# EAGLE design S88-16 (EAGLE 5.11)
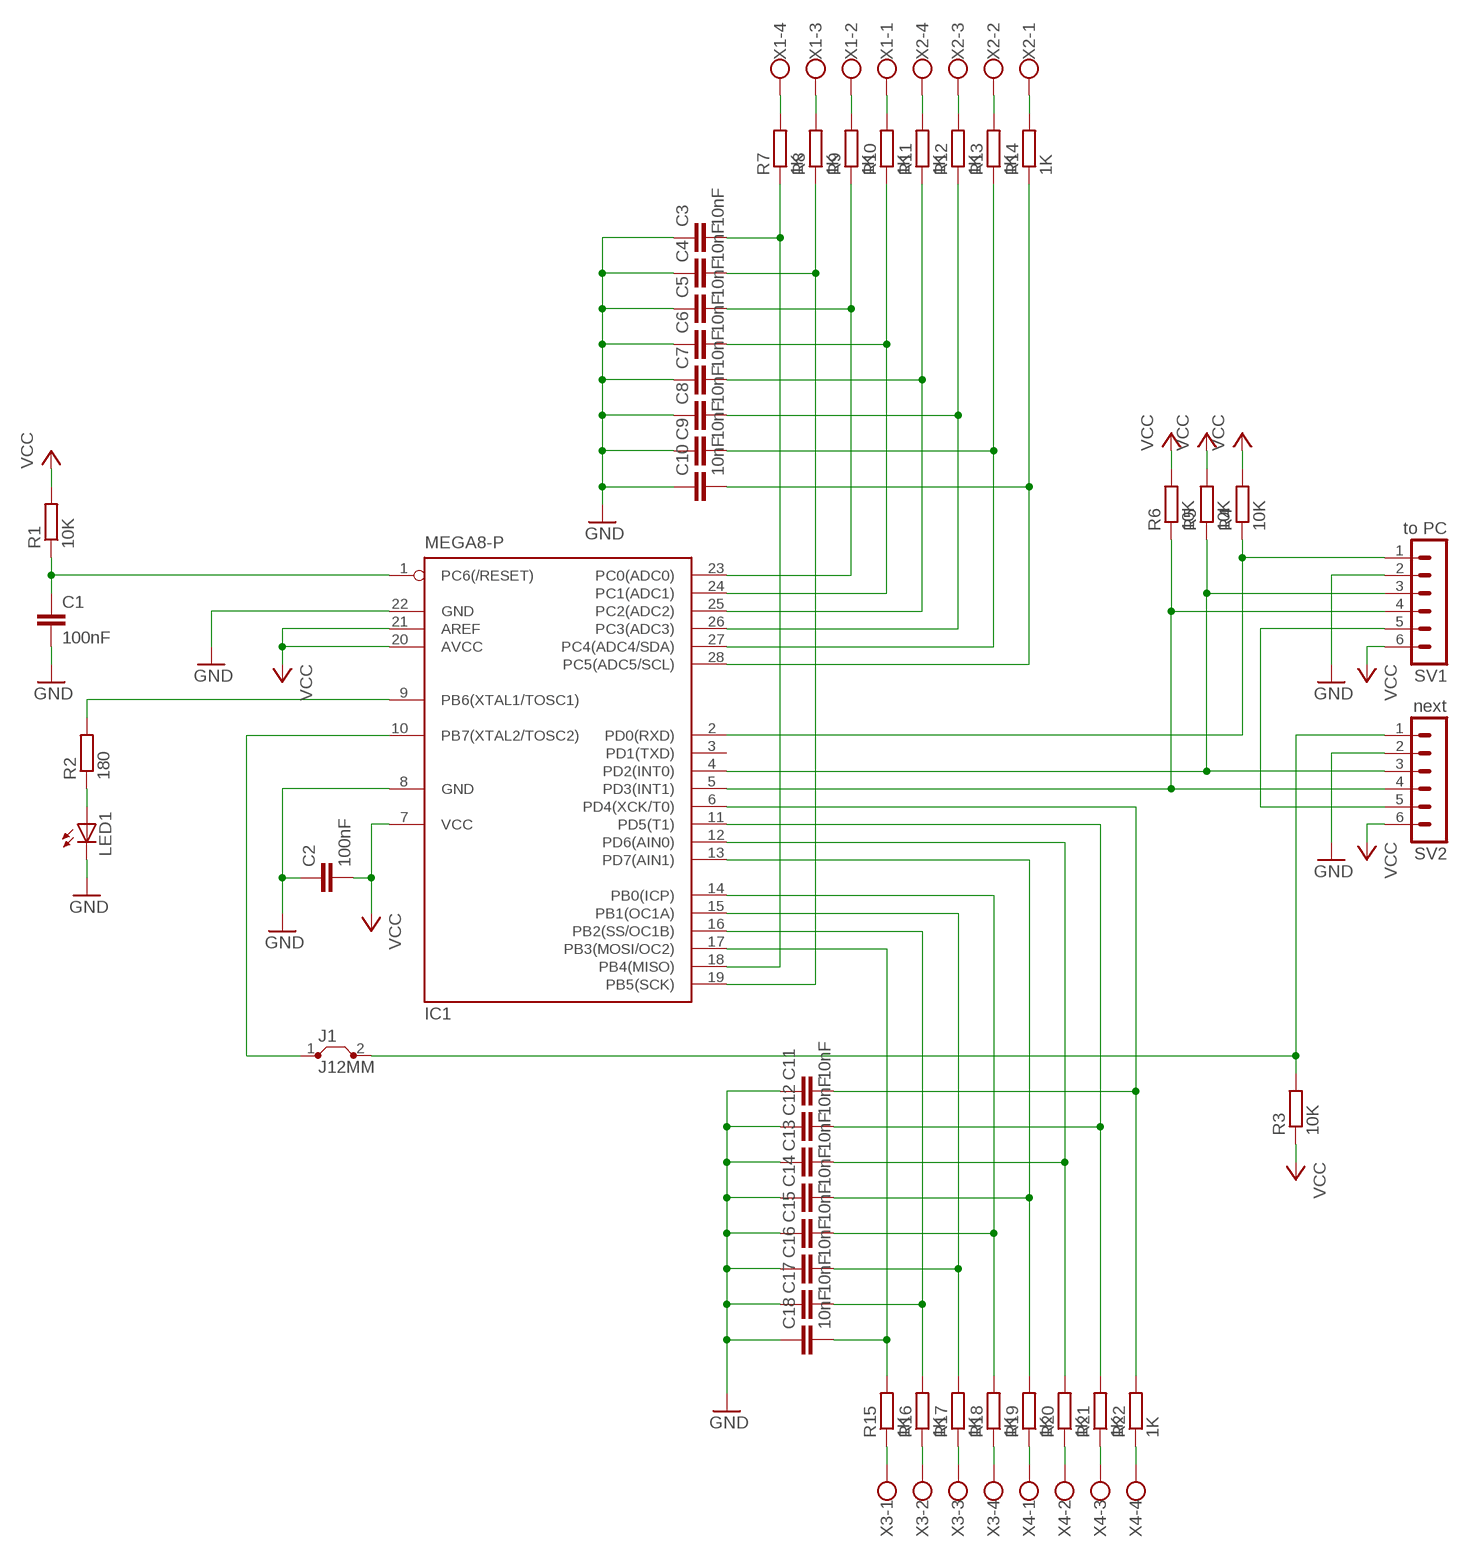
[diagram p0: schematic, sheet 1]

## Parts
C1  100nF  C-EU050-025X075  [C050-025X075]
C2  100nF  C-EU050-025X075  [C050-025X075]
C3  10nF  C-EU050-025X075  [C050-025X075]
C4  10nF  C-EU050-025X075  [C050-025X075]
C5  10nF  C-EU050-025X075  [C050-025X075]
C6  10nF  C-EU050-025X075  [C050-025X075]
C7  10nF  C-EU050-025X075  [C050-025X075]
C8  10nF  C-EU050-025X075  [C050-025X075]
C9  10nF  C-EU050-025X075  [C050-025X075]
C10  10nF  C-EU050-025X075  [C050-025X075]
C11  10nF  C-EU050-025X075  [C050-025X075]
C12  10nF  C-EU050-025X075  [C050-025X075]
C13  10nF  C-EU050-025X075  [C050-025X075]
C14  10nF  C-EU050-025X075  [C050-025X075]
C15  10nF  C-EU050-025X075  [C050-025X075]
C16  10nF  C-EU050-025X075  [C050-025X075]
C17  10nF  C-EU050-025X075  [C050-025X075]
C18  10nF  C-EU050-025X075  [C050-025X075]
IC1  MEGA8-P  [DIL28-3]
J1  J12MM  [12]
LED1  LED3MM  [LED3MM]
R1  10K  R-EU_0204/7  [0204/7]
R2  180  R-EU_0207/12  [0207/12]
R3  10K  R-EU_0207/12  [0207/12]
R4  10K  R-EU_0207/12  [0207/12]
R5  10K  R-EU_0204/7  [0204/7]
R6  10K  R-EU_0204/5  [0204/5]
R7  1K  R-EU_0207/10  [0207/10]
R8  1K  R-EU_0207/10  [0207/10]
R9  1K  R-EU_0207/10  [0207/10]
R10  1K  R-EU_0207/10  [0207/10]
R11  1K  R-EU_0207/10  [0207/10]
R12  1K  R-EU_0207/10  [0207/10]
R13  1K  R-EU_0207/10  [0207/10]
R14  1K  R-EU_0207/10  [0207/10]
R15  1K  R-EU_0207/10  [0207/10]
R16  1K  R-EU_0207/10  [0207/10]
R17  1K  R-EU_0207/10  [0207/10]
R18  1K  R-EU_0207/10  [0207/10]
R19  1K  R-EU_0207/10  [0207/10]
R20  1K  R-EU_0207/10  [0207/10]
R21  1K  R-EU_0204/7  [0204/7]
R22  1K  R-EU_0204/7  [0204/7]
SV1  to PC  MA06-1  [MA06-1]
SV2  next  MA06-1  [MA06-1]
X1  W237-4  [W237-4]
X2  W237-4  [W237-4]
X3  W237-4  [W237-4]
X4  W237-4  [W237-4]

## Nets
GND: C1.2 C2.1 C3.1 C4.1 C5.1 C6.1 C7.1 C8.1 C9.1 C10.1 C11.1 C12.1 C13.1 C14.1 C15.1 C16.1 C17.1 C18.1 IC1.8(GND) IC1.22(GND) LED1.K(C) SV1.2 SV2.2
N$1: IC1.10(PB7(XTAL2/TOSC2)) J1.1
N$2: C1.1 IC1.1(PC6(/RESET)) R1.1
N$3: IC1.9(PB6(XTAL1/TOSC1)) R2.2
N$4: LED1.A R2.1
N$5: IC1.2(PD0(RXD)) R4.1 SV1.1
N$6: IC1.4(PD2(INT0)) R5.1 SV1.3 SV2.3
N$7: IC1.5(PD3(INT1)) R6.1 SV1.4 SV2.4
N$8: SV1.5 SV2.5
N$9: C3.2 IC1.18(PB4(MISO)) R7.1
N$10: C4.2 IC1.19(PB5(SCK)) R8.1
N$11: C5.2 IC1.23(PC0(ADC0)) R9.1
N$12: C6.2 IC1.24(PC1(ADC1)) R10.1
N$13: C7.2 IC1.25(PC2(ADC2)) R11.1
N$14: C8.2 IC1.26(PC3(ADC3)) R12.1
N$15: C9.2 IC1.27(PC4(ADC4/SDA)) R13.1
N$16: C10.2 IC1.28(PC5(ADC5/SCL)) R14.1
N$17: R7.2 X1.4
N$18: R8.2 X1.3
N$19: R9.2 X1.2
N$20: R10.2 X1.1
N$21: R11.2 X2.4
N$22: R12.2 X2.3
N$23: R13.2 X2.2
N$24: R14.2 X2.1
N$25: R15.1 X3.1
N$26: R16.1 X3.2
N$27: R17.1 X3.3
N$28: R18.1 X3.4
N$29: R19.1 X4.1
N$30: R20.1 X4.2
N$31: R21.1 X4.3
N$32: R22.1 X4.4
N$33: C11.2 IC1.6(PD4(XCK/T0)) R22.2
N$34: C18.2 IC1.17(PB3(MOSI/OC2)) R15.2
N$35: C17.2 IC1.16(PB2(SS/OC1B)) R16.2
N$36: C16.2 IC1.15(PB1(OC1A)) R17.2
N$37: C15.2 IC1.14(PB0(ICP)) R18.2
N$38: C14.2 IC1.13(PD7(AIN1)) R19.2
N$39: C13.2 IC1.12(PD6(AIN0)) R20.2
N$40: C12.2 IC1.11(PD5(T1)) R21.2
N$41: J1.2 R3.2 SV2.1
VCC: C2.2 IC1.7(VCC) IC1.20(AVCC) IC1.21(AREF) R1.2 R3.1 R4.2 R5.2 R6.2 SV1.6 SV2.6
Unconnected: IC1.3(PD1(TXD))

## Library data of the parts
C1-C18 = rcl:C-EU: CAPACITOR, European symbol
IC1 = atmel:MEGA8-P: MICROCONTROLLER 8 Kbytes FLASH, 1 kbytes SRAM, 512 bytes EEPROM, USART, 4-channel 10 bit ADC, 2-channel 8 bit ADC Pin compatible with Atmega48, ATMega88, ATMega168 Source: avr.lbr; OC_FARNELL: unknown; OC_NEWARK: unknown
J1 = jumper:J: Bridge
LED1 = led:LED: LED
R1-R22 = rcl:R-EU_: RESISTOR, European symbol
SV1 SV2 = con-lstb:MA06-1: PIN HEADER; OC_FARNELL: unknown; OC_NEWARK: unknown
X1-X4 = con-wago-500:W237-4: WAGO SCREW CLAMP; OC_FARNELL: unknown; OC_NEWARK: unknown

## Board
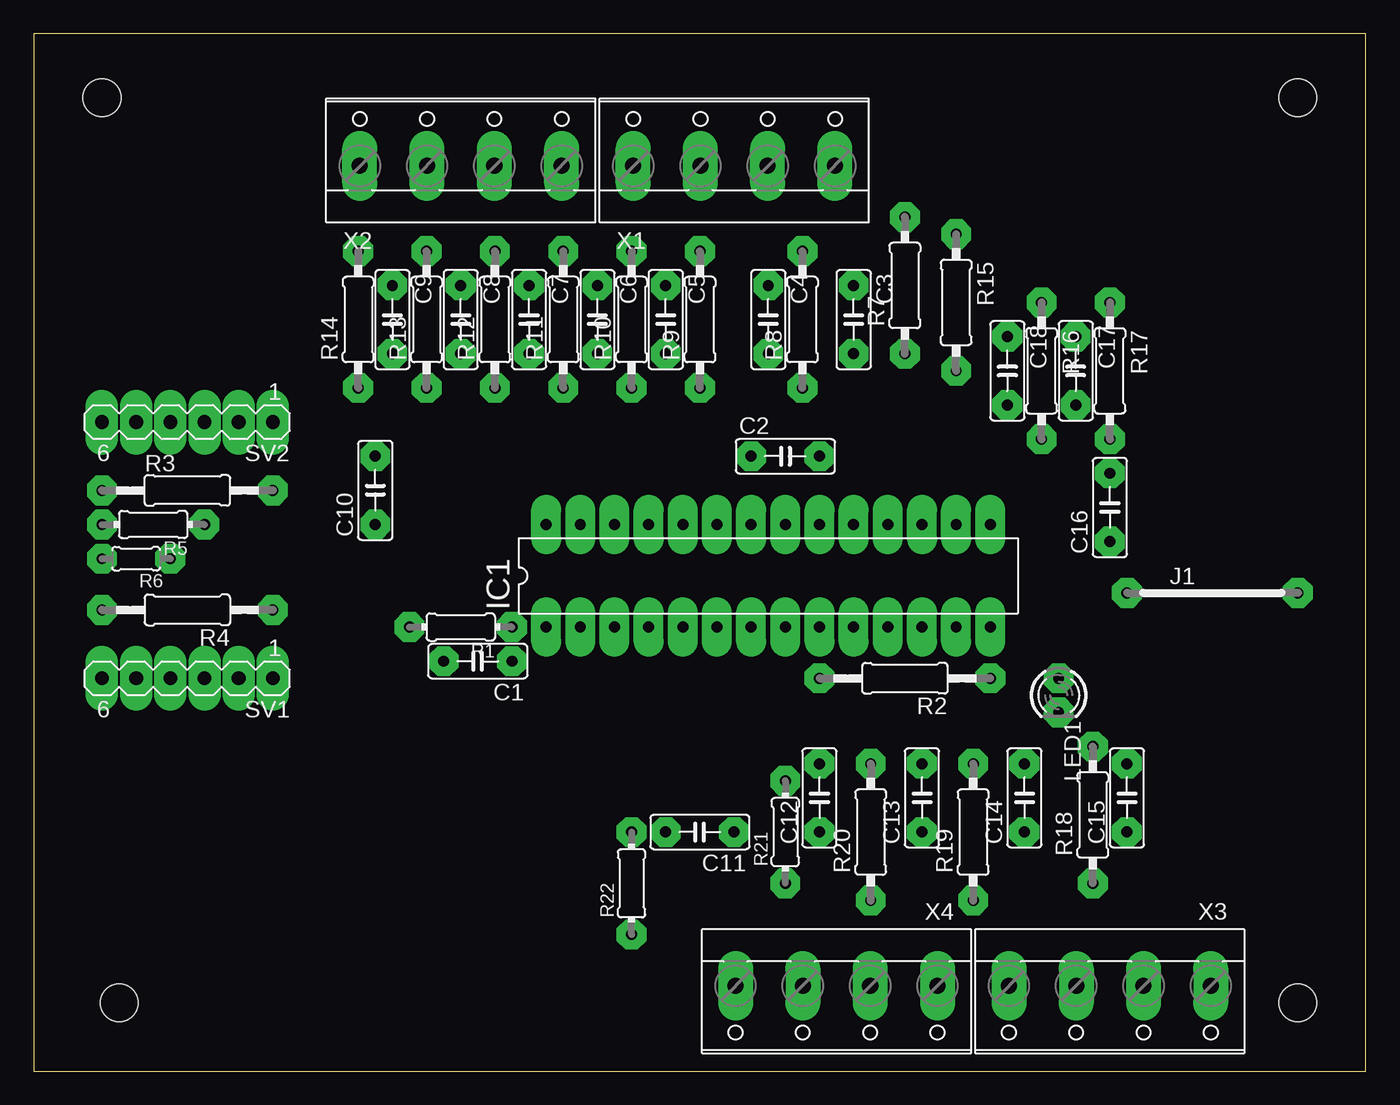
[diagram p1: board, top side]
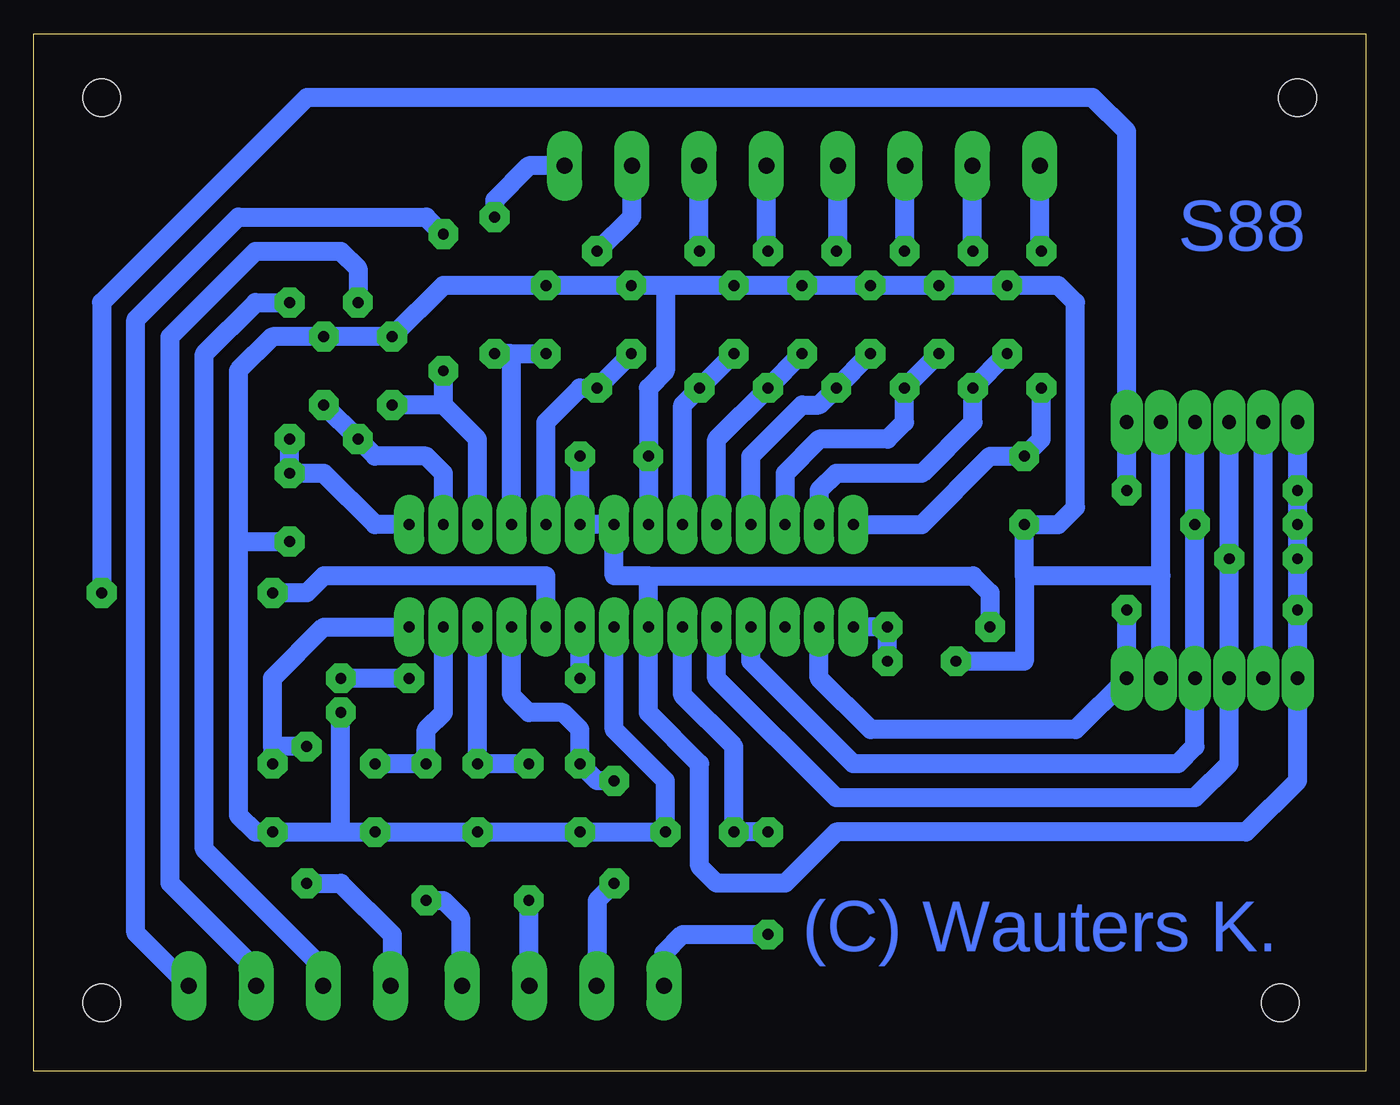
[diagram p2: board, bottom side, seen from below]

Size 99.04 x 77.14 mm. Coordinates in mm from the lower left corner, seen from the top.
Outline: 0,0 99.04,0 99.04,77.14 0,77.14 0,0
Copper layers (1*16): Top 1mm / dielectric 1.5mm / Bottom 1mm
Design rules "DRC settings large": minimum track width 1.5mm, minimum drill 26mil, track to track 0.5mm, track to pad 0.5mm, pad to pad 0.5mm, via to via 0.5mm, smd to smd 8mil, copper to edge 0.6mm, drill to drill 0.6mm, minimum pad ring 0.7mm, minimum via ring 1.2mm, stop-mask expansion 4mil, vias tented up to drill 0mil, thermal gap 10mil
Holes 2.8 mm at 5.08,72.39 93.98,72.39 6.35,5.08 93.98,5.08

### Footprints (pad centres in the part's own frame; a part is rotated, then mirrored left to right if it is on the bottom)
C050-025X075 = drill 0.813 octagon: 1 -2.54,0; 2 2.54,0
DIL28-3 = drill 0.813 long: 1 -16.51,-3.81; 2 -13.97,-3.81; 3 -11.43,-3.81; 4 -8.89,-3.81; 5 -6.35,-3.81; 6 -3.81,-3.81; 7 -1.27,-3.81; 8 1.27,-3.81; 9 3.81,-3.81; 10 6.35,-3.81; 11 8.89,-3.81; 12 11.43,-3.81; 13 13.97,-3.81; 14 16.51,-3.81; 15 16.51,3.81; 16 13.97,3.81; 17 11.43,3.81; 18 8.89,3.81; 19 6.35,3.81; 20 3.81,3.81; 21 1.27,3.81; 22 -1.27,3.81; 23 -3.81,3.81; 24 -6.35,3.81; 25 -8.89,3.81; 26 -11.43,3.81; 27 -13.97,3.81; 28 -16.51,3.81
12 = drill 0.813 pad 1.6 octagon: 1 -6.35,0; 2 6.35,0
LED3MM = drill 0.813 octagon: A -1.27,0; K 1.27,0
0204/7 = drill 0.813 octagon: 1 -3.81,0; 2 3.81,0
0207/12 = drill 0.813 octagon: 1 -6.35,0; 2 6.35,0
0204/5 = drill 0.813 octagon: 1 -2.54,0; 2 2.54,0
0207/10 = drill 0.813 octagon: 1 -5.08,0; 2 5.08,0
MA06-1 = drill 1.016 long: 1 -6.35,0; 2 -3.81,0; 3 -1.27,0; 4 1.27,0; 5 3.81,0; 6 6.35,0
W237-4 = drill 1.194 long: 1 -7.5,-1.27; 2 -2.5,-1.27; 3 2.5,-1.27; 4 7.5,-1.27

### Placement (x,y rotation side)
C1  33.02,30.48 180 top
C2  55.88,45.72 0 top
C3  60.96,55.88 270 top
C4  54.61,55.88 270 top
C5  46.99,55.88 270 top
C6  41.91,55.88 270 top
C7  36.83,55.88 270 top
C8  31.75,55.88 270 top
C9  26.67,55.88 270 top
C10  25.4,43.18 90 top
C11  49.53,17.78 180 top
C12  58.42,20.32 90 top
C13  66.04,20.32 90 top
C14  73.66,20.32 90 top
C15  81.28,20.32 90 top
C16  80.01,41.91 90 top
C17  77.47,52.07 270 top
C18  72.39,52.07 270 top
IC1  54.61,36.83 0 top
J1  87.63,35.56 0 top
LED1  76.2,27.94 270 top
R1  31.75,33.02 180 top
R2  64.77,29.21 180 top
R3  11.43,43.18 0 top
R4  11.43,34.29 180 top
R5  8.89,40.64 180 top
R6  7.62,38.1 180 top
R7  64.77,58.42 90 top
R8  57.15,55.88 90 top
R9  49.53,55.88 90 top
R10  44.45,55.88 90 top
R11  39.37,55.88 90 top
R12  34.29,55.88 90 top
R13  29.21,55.88 90 top
R14  24.13,55.88 90 top
R15  68.58,57.15 270 top
R16  74.93,52.07 270 top
R17  80.01,52.07 270 top
R18  78.74,19.05 90 top
R19  69.85,17.78 90 top
R20  62.23,17.78 90 top
R21  55.88,17.78 90 top
R22  44.45,13.97 90 top
SV1  11.43,29.21 180 top
SV2  11.43,48.26 180 top
X1  52.07,68.58 0 top
X2  31.75,68.58 0 top
X3  80.01,5.08 180 top
X4  59.69,5.08 180 top

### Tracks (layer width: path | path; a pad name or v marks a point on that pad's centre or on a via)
GND
  Bottom 1.422: 52.07,58.42 C5.1 C6.1 C7.1 C8.1 C9.1 22.86,58.42 21.59,57.15 21.59,41.91 22.86,40.64 C10.1 25.4,36.83 | 52.07,58.42 C4.1 C3.1 68.58,58.42 C18.1 C17.1 81.28,54.61 83.82,52.07 83.82,39.37 | IC1.8 55.88,25.4 52.07,21.59 C11.1 C12.1 C13.1 C14.1 76.2,17.78 | 76.2,17.78 C15.1 82.55,17.78 83.82,19.05 83.82,39.37 | 76.2,17.78 LED1.K | SV1.2 15.24,36.83 | 15.24,36.83 SV2.2 | C1.2 25.4,30.48 25.4,36.83 | 83.82,39.37 C16.1 | 15.24,36.83 25.4,36.83 | IC1.22 C2.1 53.34,50.8 52.07,52.07 52.07,58.42
N$1
  Bottom 1.422: J1.1 78.74,35.56 77.47,36.83 60.96,36.83 IC1.10
N$2
  Bottom 1.422: IC1.1 R1.1 C1.1
N$3
  Bottom 1.422: R2.2 IC1.9
N$4
  Bottom 1.422: R2.1 LED1.A
N$5
  Bottom 1.422: IC1.2 40.64,29.21 36.83,25.4 21.59,25.4 SV1.1 R4.1
N$6
  Bottom 1.422: IC1.4 45.72,30.48 38.1,22.86 13.97,22.86 12.7,24.13 SV1.3 R5.1 SV2.3
N$7
  Bottom 1.422: IC1.5 48.26,29.21 39.37,20.32 12.7,20.32 10.16,22.86 SV1.4 R6.1 SV2.4
N$8
  Bottom 1.422: SV1.5 SV2.5
N$9
  Bottom 1.422: IC1.18 63.5,53.34 | 63.5,53.34 C3.2 | 63.5,53.34 R7.1
N$10
  Bottom 1.422: C4.2 R8.1 58.42,50.8 60.96,48.26 IC1.19
N$11
  Bottom 1.422: C5.2 R9.1 50.8,49.53 IC1.23
N$12
  Bottom 1.422: C6.2 R10.1 48.26,46.99 IC1.24
N$13
  Bottom 1.422: C7.2 R11.1 40.64,49.53 41.91,49.53 45.72,45.72 IC1.25
N$14
  Bottom 1.422: C8.2 R12.1 34.29,48.26 35.56,46.99 40.64,46.99 43.18,44.45 IC1.26
N$15
  Bottom 1.422: C9.2 R13.1 29.21,48.26 33.02,44.45 39.37,44.45 40.64,43.18 IC1.27
N$16
  Bottom 1.422: R14.1 24.13,46.99 C10.2 27.94,45.72 33.02,40.64 IC1.28
N$17
  Bottom 1.422: X1.4 62.23,67.31 64.77,64.77 R7.2
N$18
  Bottom 1.422: X1.3 54.57,63.54 R8.2
N$19
  Bottom 1.422: X1.2 49.57,61 R9.2
N$20
  Bottom 1.422: X1.1 44.57,61.08 R10.2
N$21
  Bottom 1.422: X2.4 39.25,61.08 R11.2
N$22
  Bottom 1.422: X2.3 34.25,61 R12.2
N$23
  Bottom 1.422: X2.2 29.25,61 R13.2
N$24
  Bottom 1.422: X2.1 24.25,61.08 R14.2
N$25
  Bottom 1.422: R15.1 69.85,63.5 83.82,63.5 91.44,55.88 91.44,10.28 X3.1
N$26
  Bottom 1.422: R16.1 74.93,59.69 76.2,60.96 82.55,60.96 88.9,54.61 88.9,13.97 82.55,7.62 82.55,6.39 X3.2
N$27
  Bottom 1.422: R17.1 82.55,57.15 86.36,53.34 86.36,16.51 77.47,7.62 77.47,6.39 X3.3
N$28
  Bottom 1.422: R18.1 76.2,13.97 72.39,10.16 72.39,6.47 X3.4
N$29
  Bottom 1.422: R19.1 68.58,12.7 67.31,11.43 67.31,6.47 X4.1
N$30
  Bottom 1.422: R20.1 62.23,6.39 X4.2
N$31
  Bottom 1.422: R21.1 57.15,12.7 57.15,6.39 X4.3
N$32
  Bottom 1.422: X4.4 52.19,8.77 50.8,10.16 R22.1
N$33
  Bottom 1.422: IC1.6 50.8,27.94 46.99,24.13 C11.2 R22.2
N$34
  Bottom 1.422: IC1.17 66.04,46.99 68.58,49.53 | 68.58,49.53 C18.2 | 68.58,49.53 R15.2
N$35
  Bottom 1.422: IC1.16 68.58,44.45 69.85,45.72 73.66,45.72 R16.2 C17.2
N$36
  Bottom 1.422: IC1.15 73.66,40.64 77.47,44.45 C16.2 R17.2
N$37
  Bottom 1.422: IC1.14 77.47,33.02 81.28,29.21 81.28,24.13 | 81.28,24.13 C15.2 | R18.2 81.28,24.13
N$38
  Bottom 1.422: IC1.13 68.58,26.67 69.85,25.4 R19.2 C14.2
N$39
  Bottom 1.422: IC1.12 C13.2 R20.2
N$40
  Bottom 1.422: IC1.11 63.5,27.94 62.23,26.67 59.69,26.67 58.42,25.4 C12.2 57.15,21.59 R21.2
N$41
  Bottom 1.422: R3.2 SV2.1 17.78,69.85 20.32,72.39 78.74,72.39 93.98,57.15 J1.2
VCC
  Bottom 1.422: 53.34,36.83 29.21,36.83 27.94,35.56 R1.2 | 53.34,36.83 55.88,36.83 IC1.21 IC1.20 C2.2 | 53.34,36.83 IC1.7 53.34,26.67 49.53,22.86 49.53,15.24 48.26,13.97 43.18,13.97 39.37,17.78 8.89,17.78 5.08,21.59 SV1.6 R4.2 R6.2 R5.2 R3.1 SV2.6

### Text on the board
Bottom: S88 | (C) Wauters K.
